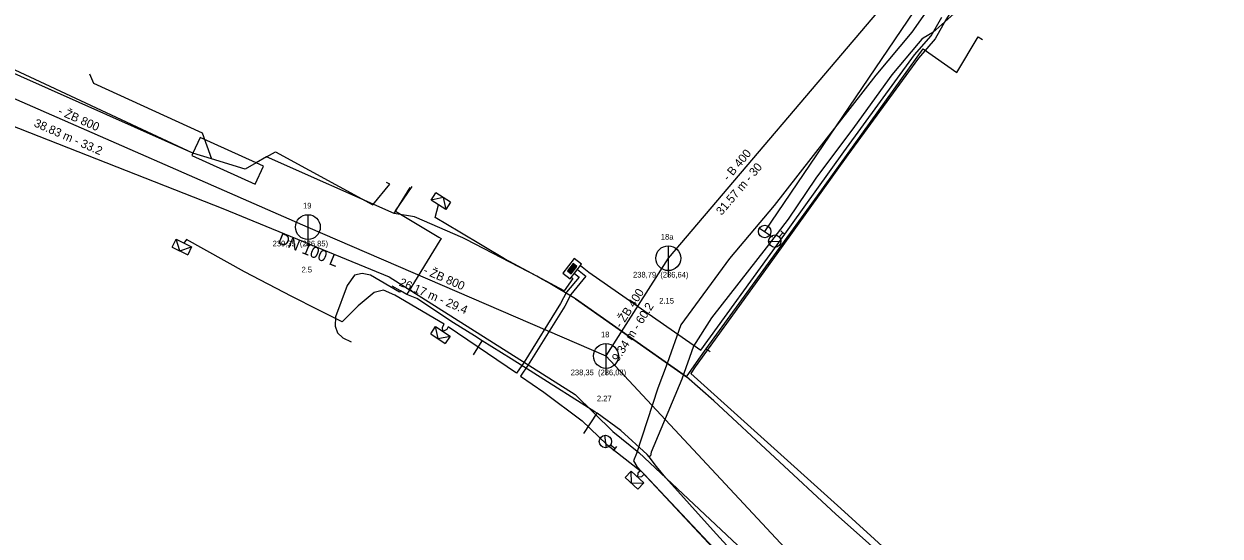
# Model space of a CAD drawing. Extents: x -600636 to -600148, y -1203980 to -1203569.
# Drawn here: x -600483.1 to -600386.7, y -1203876.3 to -1203835 of the extents above; entities that cross this region are included whole.
import ezdxf

# ---------------------------------------------------------------- set-up
doc = ezdxf.new("R2010")
doc.units = 0
for name, color, linetype in [('Cetin kolektor kabelovod', 7, 'Continuous'), ('Cetin nezaměřený', 7, 'Continuous'), ('Cetin NN přípojka', 7, 'Continuous'), ('Cetin zam průběh', 7, 'Continuous'), ('EON objekty', 7, 'Continuous'), ('EON podzemní NN', 7, 'Continuous'), ('EON podzemní VN', 7, 'Continuous'), ('GasNet STL', 7, 'Continuous'), ('Implicitní', 7, 'Continuous'), ('VaK Břeclav_kanalizace', 7, 'Continuous'), ('VaK Břeclav_kanalizace_popis', 7, 'Continuous'), ('Vak Břeclav_vodovod', 7, 'Continuous'), ('Vak Břeclav_vodovod_popis', 7, 'Continuous'), ('Vrstva 9', 7, 'Continuous')]:
    doc.layers.add(name, color=color, linetype=linetype)

# ---------------------------------------------------------------- blocks, each defined once
blk = doc.blocks.new('NN630')
at = {"layer": 'Vrstva 9'}
for points in [[(-0.003, -0.7), (-0.703, 0)], [(-0.703, -0.7), (-0.703, 0), (0.697, 0), (0.697, -0.7)], [(-0.703, -0.7), (0.697, -0.7)], [(-0.003, -0.7), (0.697, 0)]]:
    blk.add_lwpolyline(points, dxfattribs=at)
blk = doc.blocks.new('NN620')
at = {"layer": 'EON objekty'}
for points in [[(0.752, 0.004), (-0.748, 0.004)], [(-0.748, 0.004), (-0.748, -0.746)], [(0.752, -0.746), (0.752, 0.004)], [(-0.748, -0.746), (0.752, -0.746)], [(0.368, -0.18), (-0.376, -0.18)], [(-0.376, -0.18), (-0.376, -0.558)], [(-0.376, -0.558), (0.368, -0.558)], [(0.321, -0.227), (-0.329, -0.227)], [(-0.329, -0.227), (-0.329, -0.51)], [(-0.329, -0.51), (0.321, -0.51)], [(0.274, -0.274), (-0.281, -0.274)], [(-0.281, -0.274), (-0.281, -0.463)], [(-0.281, -0.463), (0.274, -0.463)], [(0.227, -0.321), (-0.234, -0.321)], [(-0.234, -0.321), (-0.234, -0.416)], [(-0.234, -0.416), (0.227, -0.416)], [(-0.193, -0.369), (0.185, -0.369)], [(0.227, -0.416), (0.227, -0.321)], [(0.274, -0.463), (0.274, -0.274)], [(0.321, -0.51), (0.321, -0.227)], [(0.368, -0.558), (0.368, -0.18)]]:
    blk.add_lwpolyline(points, dxfattribs=at)
blk = doc.blocks.new('MoSymbol 2')
at = {"layer": 'Implicitní'}
blk.add_line((0, 0.0005), (0, -0.00075), dxfattribs=at)
blk.add_circle((0, 0), 0.0005, dxfattribs=at)
blk = doc.blocks.new('MoSymbol 3')
at = {"layer": 'Implicitní'}
for p, q in [((-0.000365, -0.000365), (0.000365, 0.000365)), ((-0.000225, 0.00095), (0.000225, 0.00095)), ((0, 0.00095), (0, 0.0005))]:
    blk.add_line(p, q, dxfattribs=at)
blk.add_circle((0, 0), 0.0005, dxfattribs=at)

msp = doc.modelspace()

# ---------------------------------------------------------------- linework, layer by layer
at = {"layer": 'Cetin kolektor kabelovod'}
msp.add_lwpolyline([(-600469.44, -1203845.43), (-600488.73, -1203836.43)], dxfattribs=at)
msp.add_lwpolyline([(-600468.86, -1203844.17), (-600469.44, -1203845.43), (-600469.53, -1203845.63), (-600464.42, -1203847.94), (-600463.76, -1203846.48), (-600464.35, -1203846.21), (-600468.86, -1203844.17)], close=True, dxfattribs=at)
at = {"layer": 'Cetin nezaměřený'}
for points in [[(-600467.951, -1203845.887), (-600469.44, -1203845.43), (-600492.51, -1203835.18)], [(-600464.35, -1203846.21), (-600465.24, -1203846.72), (-600467.951, -1203845.887)]]:
    msp.add_lwpolyline(points, dxfattribs=at)
at = {"layer": 'Cetin NN přípojka'}
for points in [[(-600467.951, -1203845.887), (-600469.44, -1203845.43), (-600492.51, -1203835.18)], [(-600464.35, -1203846.21), (-600465.24, -1203846.72), (-600467.951, -1203845.887)], [(-600463.5, -1203845.73), (-600464.35, -1203846.21)], [(-600453.22, -1203850.31), (-600463.5, -1203845.73)], [(-600451.58, -1203850.57), (-600453.22, -1203850.31)], [(-600447.41, -1203852.39), (-600447.68, -1203852.27), (-600451.58, -1203850.57)], [(-600441.73, -1203855.36), (-600447.41, -1203852.39)], [(-600441.27, -1203855.62), (-600441.73, -1203855.36)], [(-600440.81, -1203855.85), (-600441.27, -1203855.62)], [(-600429.66, -1203863.46), (-600438.6, -1203857.18), (-600440.81, -1203855.85)], [(-600427.47, -1203865.39), (-600429.66, -1203863.46)], [(-600401.59, -1203888.87), (-600406.17, -1203884.71), (-600411.15, -1203880.27), (-600417.62, -1203874.52), (-600427.47, -1203865.39)]]:
    msp.add_lwpolyline(points, dxfattribs=at)
at = {"layer": 'Cetin zam průběh'}
for points in [[(-600428.66, -1203862.04), (-600428.08, -1203861.21), (-600419.11, -1203848.88), (-600410.59, -1203837.02), (-600407.88, -1203838.93), (-600406.15, -1203836.06)], [(-600406.15, -1203836.06), (-600405.81, -1203836.27)], [(-600477.78, -1203839.031), (-600477.466, -1203839.807), (-600468.712, -1203843.784), (-600467.951, -1203845.887)], [(-600463.5, -1203845.73), (-600462.8, -1203845.332), (-600454.941, -1203849.599), (-600453.58, -1203847.939), (-600453.845, -1203847.799)], [(-600463.5, -1203845.73), (-600464.35, -1203846.21)], [(-600453.22, -1203850.31), (-600463.5, -1203845.73)], [(-600453.22, -1203850.31), (-600451.93, -1203848.2)], [(-600451.58, -1203850.57), (-600453.22, -1203850.31)], [(-600447.41, -1203852.39), (-600447.68, -1203852.27), (-600451.58, -1203850.57)], [(-600441.73, -1203855.36), (-600447.41, -1203852.39)], [(-600441.27, -1203855.62), (-600441.73, -1203855.36)], [(-600440.81, -1203855.85), (-600441.27, -1203855.62)], [(-600429.66, -1203863.46), (-600438.6, -1203857.18), (-600440.81, -1203855.85)], [(-600438.6, -1203857.18), (-600429.66, -1203863.46)], [(-600428.08, -1203861.21), (-600427.76, -1203861.43)], [(-600429.66, -1203863.46), (-600428.66, -1203862.04)], [(-600427.47, -1203865.39), (-600429.66, -1203863.46)], [(-600401.59, -1203888.87), (-600406.17, -1203884.71), (-600411.15, -1203880.27), (-600417.62, -1203874.52), (-600427.47, -1203865.39)]]:
    msp.add_lwpolyline(points, dxfattribs=at)
at = {"layer": 'EON podzemní NN'}
for points in [[(-600401.18, -1203821.86), (-600400.885, -1203822.127), (-600402.931, -1203825.356), (-600408.748, -1203834.692), (-600409.616, -1203836.226), (-600410.963, -1203837.774), (-600416.658, -1203845.568), (-600422.028, -1203853.057), (-600428.974, -1203862.664), (-600429.3, -1203863.19), (-600417.22, -1203874.08), (-600405.45, -1203884.79), (-600399.15, -1203890.52), (-600398.44, -1203891.61), (-600393.326, -1203896.191), (-600393.457, -1203899.76), (-600393.232, -1203899.82)], [(-600428.496, -1203861.319), (-600422.353, -1203852.823), (-600416.981, -1203845.332), (-600411.277, -1203837.525), (-600409.944, -1203835.994), (-600409.092, -1203834.488)], [(-600438.946, -1203855.441), (-600438.834, -1203855.528), (-600439.513, -1203856.54), (-600444.33, -1203853.94), (-600447.92, -1203851.79), (-600449.93, -1203850.62), (-600449.655, -1203849.593)], [(-600438.7, -1203855.126), (-600438.312, -1203855.428), (-600439.338, -1203856.638), (-600439.814, -1203857.561), (-600442.757, -1203862.28), (-600443.365, -1203863.167), (-600448.864, -1203859.443), (-600448.985, -1203859.656), (-600449.299, -1203859.803), (-600449.333, -1203859.458), (-600449.202, -1203859.228), (-600453.16, -1203856.89), (-600454.08, -1203856.47), (-600454.84, -1203856.67), (-600456.112, -1203857.726), (-600457.402, -1203859.03), (-600459.35, -1203858.06), (-600461.46, -1203856.98), (-600465.28, -1203854.99), (-600469.95, -1203852.39), (-600470.174, -1203852.686)], [(-600438.454, -1203854.81), (-600437.764, -1203855.351), (-600438.982, -1203856.822), (-600439.466, -1203857.759), (-600442.423, -1203862.5), (-600443.035, -1203863.393), (-600441.16, -1203864.7), (-600438.07, -1203867), (-600436.07, -1203868.9), (-600433.379, -1203871.043), (-600433.572, -1203871.222), (-600433.619, -1203871.529), (-600433.266, -1203871.492), (-600433.082, -1203871.316), (-600424.84, -1203880.03), (-600423.538, -1203881.525), (-600424.029, -1203882.002), (-600424.137, -1203882.385)], [(-600438.208, -1203854.495), (-600437.523, -1203855.028), (-600428.496, -1203861.319)]]:
    msp.add_lwpolyline(points, dxfattribs=at)
at = {"layer": 'EON podzemní VN'}
msp.add_lwpolyline([(-600408.835, -1203831.858), (-600411.506, -1203835.68), (-600414.412, -1203839.145), (-600422.594, -1203849.646), (-600426.194, -1203853.932), (-600430.114, -1203859.273), (-600431.226, -1203862.375), (-600431.964, -1203864.361), (-600433.679, -1203869.626), (-600433.941, -1203870.22), (-600433.675, -1203870.696), (-600426.744, -1203878.086), (-600409.663, -1203896.312), (-600402.458, -1203904.238), (-600401.465, -1203905.565), (-600402.307, -1203907.459), (-600406.208, -1203910.525), (-600416.956, -1203919.847)], dxfattribs=at)
at = {"layer": 'GasNet STL'}
for points in [[(-600408.12, -1203834.21), (-600409.81, -1203835.72), (-600410.59, -1203836.18), (-600410.69, -1203836.24), (-600410.982, -1203836.59), (-600413.1, -1203839.13), (-600416.12, -1203843.3), (-600419.23, -1203847.46), (-600421.46, -1203850.76), (-600423.251, -1203853.057), (-600427.65, -1203858.7), (-600429.09, -1203860.98), (-600430.04, -1203863.64), (-600432.51, -1203869.52), (-600432.57, -1203869.82), (-600432.66, -1203869.91), (-600432.82, -1203869.71), (-600434.95, -1203867.78), (-600436.87, -1203866.4), (-600437.06, -1203866.29), (-600441.96, -1203863.17), (-600443.79, -1203862.01), (-600446.12, -1203860.55), (-600446.75, -1203860.15), (-600448.44, -1203859.11), (-600451.4, -1203857.16), (-600452.21, -1203856.82), (-600452.72, -1203856.53), (-600453.39, -1203856.149)], [(-600451.79, -1203848.11), (-600453.15, -1203850.09), (-600452.98, -1203850.192), (-600449.624, -1203852.197), (-600449.429, -1203852.313), (-600449.536, -1203852.486), (-600452.096, -1203856.635), (-600452.21, -1203856.82)], [(-600452.72, -1203856.53), (-600452.8, -1203856.64), (-600455.14, -1203855.28), (-600455.81, -1203855.12), (-600456.42, -1203855.28), (-600457.01, -1203856.09), (-600457.95, -1203858.62), (-600457.99, -1203859.39), (-600457.78, -1203859.91), (-600457.36, -1203860.33), (-600456.7, -1203860.63)], [(-600446.84, -1203861.68), (-600446.12, -1203860.55)], [(-600437.93, -1203868.02), (-600436.87, -1203866.4)], [(-600386.652, -1203923.85), (-600387.74, -1203922.51), (-600393.27, -1203915.72), (-600394.06, -1203914.88), (-600396.47, -1203912.28), (-600396.484, -1203912.264), (-600401.03, -1203906.96), (-600401.08, -1203906.85), (-600401.1, -1203906.75), (-600400.76, -1203904.37), (-600400.74, -1203904.28), (-600400.82, -1203904.16), (-600403.82, -1203900.09), (-600410.79, -1203892.81), (-600417.35, -1203886.31), (-600422.32, -1203881.45), (-600423.18, -1203880.61), (-600423.976, -1203879.737), (-600427.52, -1203875.85), (-600431.32, -1203871.6), (-600432.09, -1203870.68), (-600432.66, -1203869.91)]]:
    msp.add_lwpolyline(points, dxfattribs=at)
at = {"layer": 'VaK Břeclav_kanalizace'}
for p, q in [((-600410.685, -1203829.843), (-600431.13, -1203853.9)), ((-600495.75, -1203835.832), (-600460.179, -1203851.393)), ((-600460.179, -1203851.393), (-600436.153, -1203861.776)), ((-600431.13, -1203853.9), (-600436.153, -1203861.776)), ((-600436.153, -1203861.776), (-600399.213, -1203901.336))]:
    msp.add_line(p, q, dxfattribs=at)
at = {"layer": 'Vak Břeclav_vodovod'}
for points in [[(-600423.358, -1203851.751), (-600404.489, -1203823.911), (-600397.059, -1203806.587), (-600395.742, -1203804.116)], [(-600485.045, -1203842.841), (-600467.036, -1203849.899), (-600453.613, -1203855.401), (-600438.627, -1203864.89), (-600435.585, -1203867.866)], [(-600435.585, -1203867.866), (-600433.489, -1203869.554), (-600422.424, -1203879.956), (-600409.57, -1203893.38), (-600398.755, -1203905.752)]]:
    msp.add_lwpolyline(points, dxfattribs=at)

# ---------------------------------------------------------------- block references
at = {"layer": 'EON podzemní NN'}
for name, p, rotation in [('NN630', (-600449.655, -1203849.592), 147.62218886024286), ('NN630', (-600470.174, -1203852.687), -26.373124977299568), ('NN620', (-600438.578, -1203854.967), -127.94031388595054), ('NN630', (-600449.299, -1203859.803), -33.67943898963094), ('NN630', (-600433.619, -1203871.529), -43.036452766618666)]:
    msp.add_blockref(name, p, dxfattribs=dict(at, rotation=rotation))
at = {"layer": 'VaK Břeclav_kanalizace', "xscale": 1999.750031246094, "yscale": 1999.750031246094}
for p in [(-600460.179, -1203851.393), (-600431.13, -1203853.9), (-600436.153, -1203861.776)]:
    msp.add_blockref('MoSymbol 2', p, dxfattribs=at)
at = {"layer": 'Vak Břeclav_vodovod', "xscale": 999.8750156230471}
for name, p, yscale, rotation in [('MoSymbol 2', (-600423.358, -1203851.751), 999.875015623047, 55.871659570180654), ('MoSymbol 3', (-600422.543, -1203852.53), 999.8750156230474, -43.65884022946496), ('MoSymbol 3', (-600436.197, -1203868.673), 999.8750156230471, -127.19116642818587)]:
    msp.add_blockref(name, p, dxfattribs=dict(at, yscale=yscale, rotation=rotation))

# ---------------------------------------------------------------- texts
at = {"layer": 'VaK Břeclav_kanalizace_popis'}
for s, height, rotation, p in [('- ŽB 800', 0.6824, 336.37219, (-600480.374, -1203842.276)), ('38.83 m - 33.2', 0.68241, 336.37219, (-600482.315, -1203843.254)), ('- B 400', 0.6824, 49.64024, (-600426.294, -1203847.724)), ('31.57 m - 30', 0.68241, 49.64024, (-600426.826, -1203850.487)), ('- ŽB 800', 0.6824, 336.62736, (-600450.93, -1203855.108)), ('26.17 m - 29.4', 0.68241, 336.62736, (-600452.886, -1203856.089)), ('- ŽB 400', 0.6824, 57.47293, (-600434.933, -1203859.58)), ('9.34 m - 60.2', 0.68241, 57.47293, (-600435.161, -1203862.29))]:
    msp.add_text(s, height=height, rotation=rotation, dxfattribs=at).set_placement(p)
for s, height, p in [('19', 0.4549, (-600460.569, -1203849.893)), ('18a', 0.4549, (-600431.726, -1203852.4)), ('239,35  (236,85)', 0.45494, (-600463.017, -1203852.948)), ('2.5', 0.4549, (-600460.688, -1203855.048)), ('238,79  (236,64)', 0.45494, (-600433.968, -1203855.455)), ('2.15', 0.4549, (-600431.856, -1203857.555)), ('18', 0.4549, (-600436.554, -1203860.276)), ('238,35  (236,08)', 0.45494, (-600438.991, -1203863.331)), ('2.27', 0.4549, (-600436.879, -1203865.431))]:
    msp.add_text(s, height=height, dxfattribs=at).set_placement(p)
at = {"layer": 'Vak Břeclav_vodovod_popis'}
msp.add_text('DN 100 L', height=0.9099, rotation=337.7116, dxfattribs=at).set_placement((-600462.671, -1203852.672))

doc.saveas('drawing.dxf')
